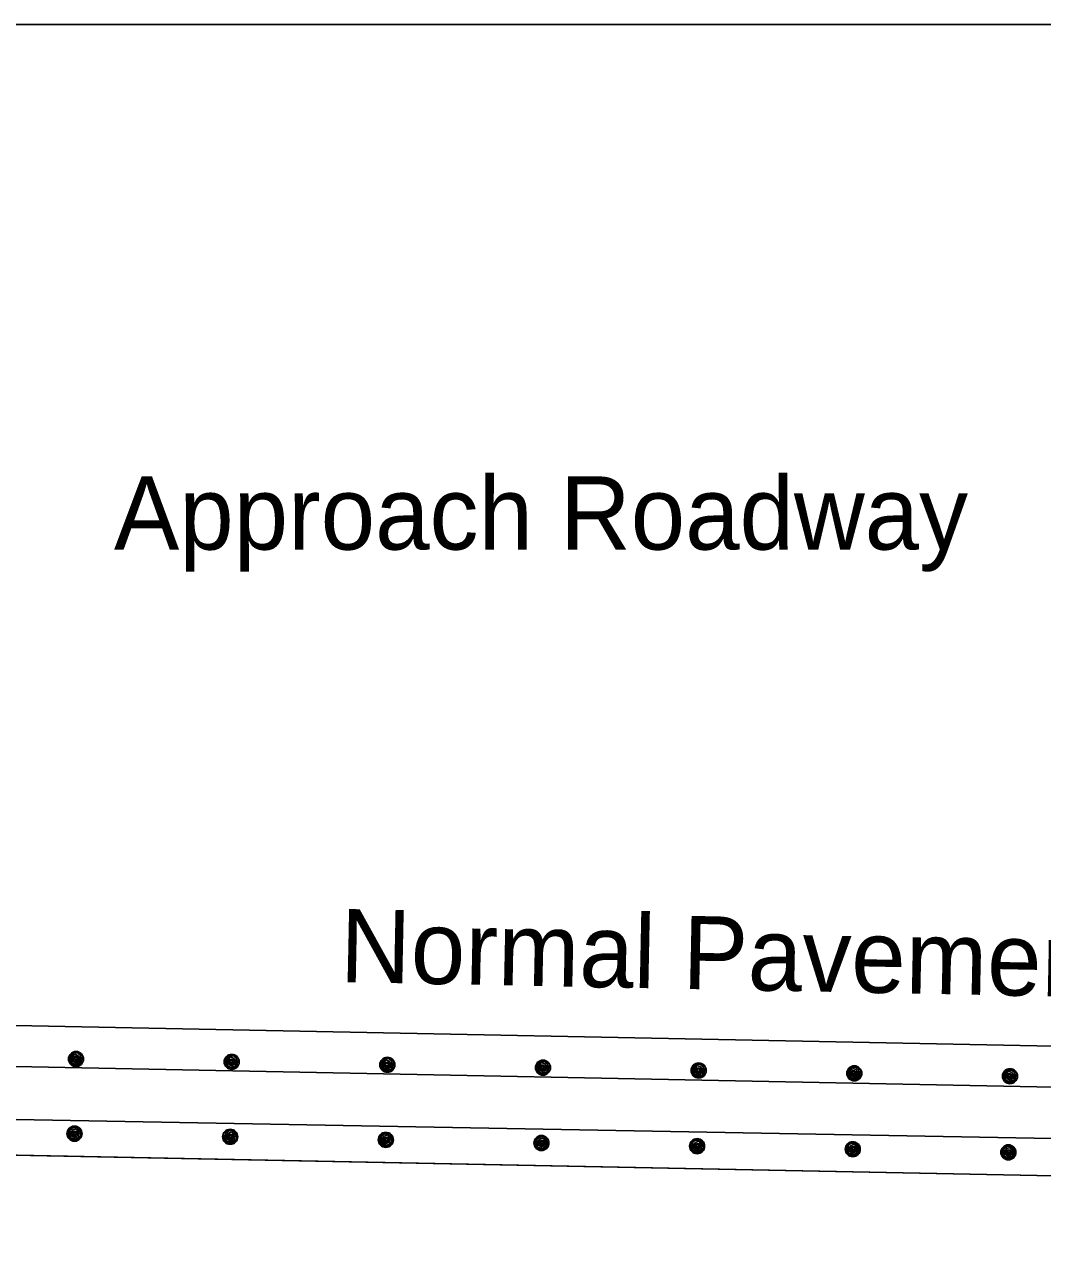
# Model space of a CAD drawing. Extents: x -2134934 to -2124557, y -2139046 to -2134021.
# Drawn here: x -2127477.9 to -2127255.3, y -2137303.2 to -2137035.9 of the extents above; entities that cross this region are included whole.
import ezdxf

# ---------------------------------------------------------------- set-up
doc = ezdxf.new("R2010")
doc.units = 0
for name, color, linetype in [('BridgeSuperStructureExisting', 7, 'Continuous'), ('dsnAlignmentStation', 7, 'Continuous'), ('dsnStdLabel', 7, 'Continuous')]:
    doc.layers.add(name, color=color, linetype=linetype)

msp = doc.modelspace()

# ---------------------------------------------------------------- linework, layer by layer
at = {"layer": 'BridgeSuperStructureExisting'}
for p, q in [((-2126773.45, -2137269.05), (-2127483.71, -2137254.79)), ((-2127483.71, -2137254.79), (-2126773.45, -2137269.05)), ((-2127483.71, -2137263.74), (-2126752.01, -2137278.43)), ((-2127484.27, -2137283.15), (-2126735.17, -2137298.18)), ((-2127483.14, -2137283.17), (-2126735.17, -2137298.18))]:
    msp.add_line(p, q, dxfattribs=at)
for points in [[(-2127468.12, -2137262.28), (-2127467.85, -2137261.74), (-2127467.55, -2137260.88), (-2127466.66, -2137260.75), (-2127465.89, -2137260.9), (-2127465.2, -2137261.48), (-2127465.3, -2137262.3), (-2127465.46, -2137263.17), (-2127466.17, -2137263.56), (-2127466.9, -2137263.61), (-2127467.84, -2137263.06), (-2127467.89, -2137262.42), (-2127467.64, -2137261.56), (-2127467.06, -2137260.87), (-2127466.23, -2137260.92), (-2127465.59, -2137261.5), (-2127465.54, -2137262.29), (-2127465.75, -2137263.15), (-2127466.24, -2137263.26), (-2127466.84, -2137263.42), (-2127467.54, -2137262.98), (-2127467.5, -2137262.35), (-2127467.35, -2137261.63), (-2127466.93, -2137261.12), (-2127466.21, -2137261.41), (-2127465.82, -2137261.97), (-2127465.82, -2137262.71), (-2127466.22, -2137262.87), (-2127466.67, -2137263.09), (-2127467.23, -2137262.71), (-2127467.34, -2137262.17), (-2127467.06, -2137261.69), (-2127466.53, -2137261.68), (-2127466.16, -2137261.95), (-2127466.04, -2137262.45), (-2127466.26, -2137262.68), (-2127466.56, -2137262.8), (-2127466.97, -2137262.53), (-2127467.05, -2137262.18), (-2127466.83, -2137261.86), (-2127466.54, -2137261.92), (-2127466.37, -2137262.18), (-2127466.39, -2137262.52), (-2127466.63, -2137262.51), (-2127466.76, -2137262.2)], [(-2127434.09, -2137262.92), (-2127433.82, -2137262.36), (-2127433.51, -2137261.51), (-2127432.63, -2137261.37), (-2127431.85, -2137261.52), (-2127431.16, -2137262.11), (-2127431.27, -2137262.93), (-2127431.43, -2137263.8), (-2127432.13, -2137264.19), (-2127432.87, -2137264.23), (-2127433.81, -2137263.68), (-2127433.86, -2137263.04), (-2127433.61, -2137262.19), (-2127433.02, -2137261.49), (-2127432.2, -2137261.55), (-2127431.56, -2137262.13), (-2127431.51, -2137262.91), (-2127431.72, -2137263.78), (-2127432.21, -2137263.89), (-2127432.8, -2137264.04), (-2127433.51, -2137263.61), (-2127433.47, -2137262.98), (-2127433.32, -2137262.25), (-2127432.89, -2137261.74), (-2127432.18, -2137262.04), (-2127431.78, -2137262.6), (-2127431.78, -2137263.33), (-2127432.18, -2137263.5), (-2127432.64, -2137263.71), (-2127433.19, -2137263.33), (-2127433.31, -2137262.79), (-2127433.03, -2137262.32), (-2127432.49, -2137262.31), (-2127432.12, -2137262.58), (-2127432.01, -2137263.07), (-2127432.22, -2137263.3), (-2127432.52, -2137263.43), (-2127432.94, -2137263.16), (-2127433.01, -2137262.81), (-2127432.8, -2137262.48), (-2127432.51, -2137262.55), (-2127432.33, -2137262.81), (-2127432.36, -2137263.15), (-2127432.6, -2137263.13), (-2127432.73, -2137262.83)], [(-2127400.05, -2137263.54), (-2127399.78, -2137262.99), (-2127399.48, -2137262.13), (-2127398.59, -2137262), (-2127397.82, -2137262.15), (-2127397.13, -2137262.73), (-2127397.24, -2137263.56), (-2127397.39, -2137264.42), (-2127398.1, -2137264.81), (-2127398.84, -2137264.86), (-2127399.77, -2137264.31), (-2127399.83, -2137263.67), (-2127399.57, -2137262.81), (-2127398.99, -2137262.12), (-2127398.17, -2137262.17), (-2127397.52, -2137262.76), (-2127397.48, -2137263.54), (-2127397.68, -2137264.4), (-2127398.18, -2137264.51), (-2127398.77, -2137264.67), (-2127399.47, -2137264.23), (-2127399.43, -2137263.6), (-2127399.28, -2137262.88), (-2127398.86, -2137262.37), (-2127398.15, -2137262.67), (-2127397.75, -2137263.23), (-2127397.75, -2137263.96), (-2127398.15, -2137264.13), (-2127398.6, -2137264.34), (-2127399.16, -2137263.96), (-2127399.28, -2137263.42), (-2127399, -2137262.95), (-2127398.46, -2137262.93), (-2127398.09, -2137263.2), (-2127397.98, -2137263.7), (-2127398.19, -2137263.93), (-2127398.49, -2137264.05), (-2127398.91, -2137263.78), (-2127398.98, -2137263.44), (-2127398.76, -2137263.11), (-2127398.48, -2137263.18), (-2127398.3, -2137263.43), (-2127398.32, -2137263.78), (-2127398.56, -2137263.76), (-2127398.69, -2137263.45)], [(-2127366.02, -2137264.17), (-2127365.75, -2137263.62), (-2127365.45, -2137262.76), (-2127364.56, -2137262.62), (-2127363.79, -2137262.78), (-2127363.1, -2137263.36), (-2127363.2, -2137264.18), (-2127363.36, -2137265.05), (-2127364.07, -2137265.44), (-2127364.8, -2137265.48), (-2127365.74, -2137264.94), (-2127365.79, -2137264.3), (-2127365.54, -2137263.44), (-2127364.96, -2137262.74), (-2127364.13, -2137262.8), (-2127363.49, -2137263.38), (-2127363.44, -2137264.16), (-2127363.65, -2137265.03), (-2127364.14, -2137265.14), (-2127364.74, -2137265.29), (-2127365.44, -2137264.86), (-2127365.4, -2137264.23), (-2127365.25, -2137263.5), (-2127364.83, -2137263), (-2127364.11, -2137263.29), (-2127363.72, -2137263.85), (-2127363.72, -2137264.58), (-2127364.12, -2137264.75), (-2127364.57, -2137264.97), (-2127365.13, -2137264.59), (-2127365.24, -2137264.04), (-2127364.96, -2137263.57), (-2127364.43, -2137263.56), (-2127364.06, -2137263.83), (-2127363.94, -2137264.32), (-2127364.15, -2137264.55), (-2127364.45, -2137264.68), (-2127364.87, -2137264.41), (-2127364.95, -2137264.06), (-2127364.73, -2137263.74), (-2127364.44, -2137263.8), (-2127364.27, -2137264.06), (-2127364.29, -2137264.4), (-2127364.53, -2137264.38), (-2127364.66, -2137264.08)], [(-2127331.99, -2137264.79), (-2127331.72, -2137264.25), (-2127331.41, -2137263.39), (-2127330.52, -2137263.25), (-2127329.75, -2137263.4), (-2127329.06, -2137263.98), (-2127329.16, -2137264.81), (-2127329.32, -2137265.67), (-2127330.03, -2137266.06), (-2127330.77, -2137266.11), (-2127331.71, -2137265.56), (-2127331.76, -2137264.93), (-2127331.51, -2137264.06), (-2127330.92, -2137263.37), (-2127330.1, -2137263.43), (-2127329.45, -2137264.01), (-2127329.41, -2137264.79), (-2127329.62, -2137265.65), (-2127330.11, -2137265.77), (-2127330.7, -2137265.92), (-2127331.41, -2137265.48), (-2127331.36, -2137264.85), (-2127331.22, -2137264.13), (-2127330.79, -2137263.62), (-2127330.08, -2137263.92), (-2127329.68, -2137264.48), (-2127329.68, -2137265.21), (-2127330.08, -2137265.38), (-2127330.54, -2137265.59), (-2127331.09, -2137265.21), (-2127331.21, -2137264.67), (-2127330.93, -2137264.2), (-2127330.39, -2137264.19), (-2127330.02, -2137264.45), (-2127329.91, -2137264.95), (-2127330.12, -2137265.18), (-2127330.42, -2137265.31), (-2127330.84, -2137265.03), (-2127330.91, -2137264.69), (-2127330.7, -2137264.36), (-2127330.41, -2137264.43), (-2127330.23, -2137264.68), (-2127330.26, -2137265.03), (-2127330.5, -2137265.01), (-2127330.62, -2137264.71)], [(-2127297.95, -2137265.42), (-2127297.68, -2137264.87), (-2127297.38, -2137264.01), (-2127296.49, -2137263.88), (-2127295.72, -2137264.03), (-2127295.03, -2137264.61), (-2127295.13, -2137265.43), (-2127295.29, -2137266.3), (-2127296, -2137266.69), (-2127296.73, -2137266.74), (-2127297.67, -2137266.19), (-2127297.73, -2137265.55), (-2127297.47, -2137264.69), (-2127296.89, -2137263.99), (-2127296.06, -2137264.05), (-2127295.42, -2137264.63), (-2127295.38, -2137265.42), (-2127295.58, -2137266.28), (-2127296.08, -2137266.39), (-2127296.67, -2137266.54), (-2127297.37, -2137266.11), (-2127297.33, -2137265.48), (-2127297.18, -2137264.76), (-2127296.76, -2137264.25), (-2127296.05, -2137264.54), (-2127295.65, -2137265.1), (-2127295.65, -2137265.84), (-2127296.05, -2137266), (-2127296.5, -2137266.22), (-2127297.06, -2137265.84), (-2127297.17, -2137265.29), (-2127296.89, -2137264.82), (-2127296.36, -2137264.81), (-2127295.99, -2137265.08), (-2127295.87, -2137265.58), (-2127296.09, -2137265.8), (-2127296.38, -2137265.93), (-2127296.81, -2137265.66), (-2127296.88, -2137265.31), (-2127296.66, -2137264.99), (-2127296.37, -2137265.05), (-2127296.2, -2137265.31), (-2127296.22, -2137265.65), (-2127296.46, -2137265.63), (-2127296.59, -2137265.33)], [(-2127263.92, -2137266.04), (-2127263.65, -2137265.5), (-2127263.35, -2137264.64), (-2127262.46, -2137264.5), (-2127261.69, -2137264.65), (-2127260.99, -2137265.24), (-2127261.1, -2137266.06), (-2127261.26, -2137266.93), (-2127261.97, -2137267.32), (-2127262.7, -2137267.37), (-2127263.64, -2137266.81), (-2127263.69, -2137266.18), (-2127263.44, -2137265.32), (-2127262.86, -2137264.62), (-2127262.03, -2137264.68), (-2127261.39, -2137265.26), (-2127261.34, -2137266.04), (-2127261.55, -2137266.91), (-2127262.04, -2137267.02), (-2127262.64, -2137267.17), (-2127263.34, -2137266.73), (-2127263.3, -2137266.11), (-2127263.15, -2137265.38), (-2127262.73, -2137264.88), (-2127262.01, -2137265.17), (-2127261.61, -2137265.73), (-2127261.61, -2137266.47), (-2127262.02, -2137266.63), (-2127262.47, -2137266.84), (-2127263.03, -2137266.46), (-2127263.14, -2137265.92), (-2127262.86, -2137265.45), (-2127262.33, -2137265.44), (-2127261.96, -2137265.71), (-2127261.84, -2137266.2), (-2127262.05, -2137266.43), (-2127262.35, -2137266.56), (-2127262.77, -2137266.29), (-2127262.85, -2137265.94), (-2127262.63, -2137265.61), (-2127262.34, -2137265.68), (-2127262.16, -2137265.94), (-2127262.19, -2137266.28), (-2127262.43, -2137266.26), (-2127262.56, -2137265.96)], [(-2127465.41, -2137278.66), (-2127465.67, -2137278.1), (-2127465.94, -2137277.23), (-2127466.82, -2137277.07), (-2127467.59, -2137277.19), (-2127468.3, -2137277.74), (-2127468.23, -2137278.57), (-2127468.11, -2137279.44), (-2127467.42, -2137279.85), (-2127466.68, -2137279.93), (-2127465.73, -2137279.42), (-2127465.64, -2137278.78), (-2127465.86, -2137277.91), (-2127466.42, -2137277.2), (-2127467.25, -2137277.22), (-2127467.92, -2137277.78), (-2127467.99, -2137278.56), (-2127467.82, -2137279.43), (-2127467.33, -2137279.56), (-2127466.74, -2137279.74), (-2127466.02, -2137279.33), (-2127466.04, -2137278.69), (-2127466.16, -2137277.97), (-2127466.56, -2137277.45), (-2127467.28, -2137277.71), (-2127467.71, -2137278.26), (-2127467.73, -2137278.99), (-2127467.34, -2137279.17), (-2127466.89, -2137279.4), (-2127466.32, -2137279.05), (-2127466.19, -2137278.51), (-2127466.44, -2137278.03), (-2127466.98, -2137277.99), (-2127467.36, -2137278.25), (-2127467.5, -2137278.74), (-2127467.3, -2137278.98), (-2127467, -2137279.11), (-2127466.57, -2137278.86), (-2127466.48, -2137278.51), (-2127466.68, -2137278.18), (-2127466.97, -2137278.24), (-2127467.16, -2137278.49), (-2127467.15, -2137278.83), (-2127466.91, -2137278.82), (-2127466.77, -2137278.52)], [(-2127431.38, -2137279.34), (-2127431.64, -2137278.78), (-2127431.9, -2137277.92), (-2127432.78, -2137277.75), (-2127433.56, -2137277.87), (-2127434.27, -2137278.43), (-2127434.2, -2137279.25), (-2127434.08, -2137280.12), (-2127433.38, -2137280.54), (-2127432.65, -2137280.61), (-2127431.69, -2137280.1), (-2127431.61, -2137279.46), (-2127431.83, -2137278.6), (-2127432.39, -2137277.88), (-2127433.21, -2137277.91), (-2127433.88, -2137278.46), (-2127433.95, -2137279.24), (-2127433.79, -2137280.11), (-2127433.29, -2137280.24), (-2127432.7, -2137280.42), (-2127431.99, -2137280.01), (-2127432, -2137279.38), (-2127432.12, -2137278.65), (-2127432.53, -2137278.13), (-2127433.25, -2137278.4), (-2127433.67, -2137278.94), (-2127433.7, -2137279.67), (-2127433.3, -2137279.85), (-2127432.86, -2137280.08), (-2127432.29, -2137279.73), (-2127432.16, -2137279.19), (-2127432.41, -2137278.71), (-2127432.95, -2137278.68), (-2127433.33, -2137278.93), (-2127433.46, -2137279.42), (-2127433.26, -2137279.66), (-2127432.96, -2137279.8), (-2127432.54, -2137279.54), (-2127432.45, -2137279.2), (-2127432.65, -2137278.86), (-2127432.94, -2137278.92), (-2127433.13, -2137279.16), (-2127433.12, -2137279.51), (-2127432.87, -2137279.5), (-2127432.74, -2137279.21)], [(-2127397.35, -2137280.02), (-2127397.6, -2137279.47), (-2127397.87, -2137278.6), (-2127398.75, -2137278.43), (-2127399.52, -2137278.55), (-2127400.24, -2137279.11), (-2127400.16, -2137279.93), (-2127400.05, -2137280.8), (-2127399.35, -2137281.22), (-2127398.62, -2137281.3), (-2127397.66, -2137280.79), (-2127397.58, -2137280.15), (-2127397.8, -2137279.28), (-2127398.36, -2137278.57), (-2127399.18, -2137278.59), (-2127399.85, -2137279.14), (-2127399.92, -2137279.93), (-2127399.75, -2137280.79), (-2127399.26, -2137280.93), (-2127398.67, -2137281.11), (-2127397.95, -2137280.7), (-2127397.98, -2137280.06), (-2127398.09, -2137279.34), (-2127398.49, -2137278.81), (-2127399.22, -2137279.08), (-2127399.64, -2137279.62), (-2127399.67, -2137280.36), (-2127399.28, -2137280.54), (-2127398.83, -2137280.77), (-2127398.25, -2137280.41), (-2127398.13, -2137279.87), (-2127398.38, -2137279.39), (-2127398.92, -2137279.36), (-2127399.3, -2137279.61), (-2127399.43, -2137280.11), (-2127399.23, -2137280.35), (-2127398.93, -2137280.48), (-2127398.51, -2137280.23), (-2127398.42, -2137279.88), (-2127398.62, -2137279.55), (-2127398.91, -2137279.6), (-2127399.1, -2137279.85), (-2127399.09, -2137280.19), (-2127398.84, -2137280.19), (-2127398.71, -2137279.89)], [(-2127363.32, -2137280.71), (-2127363.57, -2137280.15), (-2127363.84, -2137279.28), (-2127364.72, -2137279.11), (-2127365.49, -2137279.23), (-2127366.21, -2137279.79), (-2127366.13, -2137280.61), (-2127366.01, -2137281.49), (-2127365.32, -2137281.91), (-2127364.59, -2137281.98), (-2127363.63, -2137281.47), (-2127363.55, -2137280.83), (-2127363.77, -2137279.96), (-2127364.32, -2137279.25), (-2127365.15, -2137279.27), (-2127365.82, -2137279.83), (-2127365.89, -2137280.61), (-2127365.72, -2137281.48), (-2127365.23, -2137281.61), (-2127364.64, -2137281.79), (-2127363.92, -2137281.38), (-2127363.94, -2137280.75), (-2127364.06, -2137280.02), (-2127364.46, -2137279.49), (-2127365.18, -2137279.76), (-2127365.61, -2137280.31), (-2127365.63, -2137281.04), (-2127365.24, -2137281.22), (-2127364.79, -2137281.45), (-2127364.22, -2137281.1), (-2127364.09, -2137280.55), (-2127364.35, -2137280.08), (-2127364.89, -2137280.04), (-2127365.27, -2137280.3), (-2127365.4, -2137280.79), (-2127365.2, -2137281.03), (-2127364.9, -2137281.17), (-2127364.47, -2137280.91), (-2127364.38, -2137280.56), (-2127364.59, -2137280.23), (-2127364.88, -2137280.29), (-2127365.06, -2137280.53), (-2127365.06, -2137280.88), (-2127364.81, -2137280.87), (-2127364.68, -2137280.57)], [(-2127329.28, -2137281.39), (-2127329.54, -2137280.83), (-2127329.8, -2137279.96), (-2127330.68, -2137279.8), (-2127331.46, -2137279.92), (-2127332.17, -2137280.47), (-2127332.1, -2137281.3), (-2127331.98, -2137282.17), (-2127331.29, -2137282.59), (-2127330.55, -2137282.66), (-2127329.6, -2137282.15), (-2127329.51, -2137281.51), (-2127329.74, -2137280.64), (-2127330.29, -2137279.93), (-2127331.12, -2137279.96), (-2127331.78, -2137280.51), (-2127331.86, -2137281.29), (-2127331.69, -2137282.16), (-2127331.2, -2137282.29), (-2127330.61, -2137282.47), (-2127329.89, -2137282.06), (-2127329.91, -2137281.43), (-2127330.02, -2137280.7), (-2127330.43, -2137280.18), (-2127331.15, -2137280.44), (-2127331.58, -2137280.99), (-2127331.6, -2137281.72), (-2127331.21, -2137281.91), (-2127330.76, -2137282.13), (-2127330.19, -2137281.78), (-2127330.06, -2137281.24), (-2127330.31, -2137280.76), (-2127330.85, -2137280.73), (-2127331.23, -2137280.98), (-2127331.37, -2137281.47), (-2127331.17, -2137281.71), (-2127330.87, -2137281.85), (-2127330.44, -2137281.59), (-2127330.35, -2137281.25), (-2127330.55, -2137280.91), (-2127330.84, -2137280.97), (-2127331.03, -2137281.22), (-2127331.02, -2137281.56), (-2127330.78, -2137281.55), (-2127330.64, -2137281.26)], [(-2127295.25, -2137282.08), (-2127295.5, -2137281.52), (-2127295.77, -2137280.65), (-2127296.65, -2137280.48), (-2127297.43, -2137280.6), (-2127298.14, -2137281.16), (-2127298.07, -2137281.98), (-2127297.94, -2137282.86), (-2127297.25, -2137283.27), (-2127296.52, -2137283.35), (-2127295.56, -2137282.83), (-2127295.48, -2137282.2), (-2127295.7, -2137281.33), (-2127296.26, -2137280.61), (-2127297.09, -2137280.64), (-2127297.75, -2137281.19), (-2127297.83, -2137281.97), (-2127297.66, -2137282.85), (-2127297.16, -2137282.97), (-2127296.57, -2137283.15), (-2127295.86, -2137282.74), (-2127295.88, -2137282.11), (-2127295.99, -2137281.38), (-2127296.4, -2137280.86), (-2127297.12, -2137281.13), (-2127297.54, -2137281.67), (-2127297.57, -2137282.41), (-2127297.18, -2137282.59), (-2127296.73, -2137282.82), (-2127296.16, -2137282.46), (-2127296.03, -2137281.92), (-2127296.28, -2137281.44), (-2127296.82, -2137281.41), (-2127297.2, -2137281.66), (-2127297.34, -2137282.15), (-2127297.13, -2137282.39), (-2127296.84, -2137282.53), (-2127296.41, -2137282.27), (-2127296.32, -2137281.93), (-2127296.52, -2137281.59), (-2127296.81, -2137281.65), (-2127297, -2137281.9), (-2127296.99, -2137282.24), (-2127296.75, -2137282.24), (-2127296.61, -2137281.94)], [(-2127261.22, -2137282.76), (-2127261.47, -2137282.2), (-2127261.74, -2137281.33), (-2127262.62, -2137281.16), (-2127263.39, -2137281.28), (-2127264.11, -2137281.84), (-2127264.04, -2137282.66), (-2127263.92, -2137283.54), (-2127263.22, -2137283.95), (-2127262.49, -2137284.03), (-2127261.53, -2137283.52), (-2127261.45, -2137282.88), (-2127261.67, -2137282.01), (-2127262.23, -2137281.3), (-2127263.05, -2137281.32), (-2127263.72, -2137281.88), (-2127263.79, -2137282.66), (-2127263.62, -2137283.53), (-2127263.13, -2137283.66), (-2127262.54, -2137283.84), (-2127261.82, -2137283.43), (-2127261.84, -2137282.8), (-2127261.96, -2137282.07), (-2127262.37, -2137281.55), (-2127263.09, -2137281.81), (-2127263.51, -2137282.35), (-2127263.54, -2137283.09), (-2127263.14, -2137283.27), (-2127262.7, -2137283.5), (-2127262.12, -2137283.15), (-2127262, -2137282.61), (-2127262.25, -2137282.12), (-2127262.79, -2137282.09), (-2127263.17, -2137282.35), (-2127263.3, -2137282.84), (-2127263.1, -2137283.08), (-2127262.8, -2137283.21), (-2127262.37, -2137282.96), (-2127262.29, -2137282.62), (-2127262.49, -2137282.28), (-2127262.78, -2137282.34), (-2127262.97, -2137282.59), (-2127262.96, -2137282.93), (-2127262.71, -2137282.92), (-2127262.58, -2137282.62)]]:
    msp.add_lwpolyline(points, dxfattribs=at)
for centre in [(-2127466.6, -2137262.22), (-2127432.56, -2137262.84), (-2127398.53, -2137263.47), (-2127364.5, -2137264.1), (-2127330.46, -2137264.72), (-2127296.43, -2137265.35), (-2127262.39, -2137265.98), (-2127466.93, -2137278.53), (-2127432.9, -2137279.22), (-2127398.87, -2137279.9), (-2127364.84, -2137280.58), (-2127330.8, -2137281.27), (-2127296.77, -2137281.95), (-2127262.74, -2137282.63)]:
    msp.add_circle(centre, 1.65, dxfattribs=at)
at = {"layer": 'dsnAlignmentStation'}
msp.add_lwpolyline([(-2127734.44, -2137035.95), (-2124599.45, -2137035.95), (-2124599.45, -2139045.94), (-2127734.44, -2139045.94)], close=True, dxfattribs=at)
at = {"layer": 'dsnStdLabel'}
msp.add_line((-2126752.19, -2137288.89), (-2127483.74, -2137275.34), dxfattribs=at)

# ---------------------------------------------------------------- texts
msp.add_text('Approach Roadway', height=16, dxfattribs=at).set_placement((-2127458.3, -2137150.8))
msp.add_text('Normal Pavement Slope', height=16, rotation=358.8502, dxfattribs=at).set_placement((-2127408.97, -2137245.37))

doc.saveas('drawing.dxf')
